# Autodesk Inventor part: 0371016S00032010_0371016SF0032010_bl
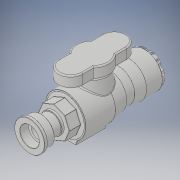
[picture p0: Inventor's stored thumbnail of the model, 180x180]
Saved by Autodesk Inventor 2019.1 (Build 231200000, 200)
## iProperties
Created: 2022-04
Part Number: 0371016S00032010_0371016SF0032010_bl
Material: Generic
Description: PA Ball Valve Series 1 32mm x Free Nut Female 1''
Document SubType Name: Modeling
Designer: Lenora
Density: 1 g/cm^3
Appearance: Default
Author: Lenora
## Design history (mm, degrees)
derived "0371016.ipt"
feature "Solid1::0371016.ipt" dims "ScaleForDerivedMember" = 10
tag "TaggingFeature1"
body "Solid1"
other parameters: "d0" = 192 [user parameter], "d16" = 92.16 [user parameter], "d19" = 1 [user parameter], "d20" = 48 [user parameter], "d22" = 85 deg [user parameter], "d25" = 1 [user parameter], "d34" = 34.56 [user parameter], "d35" = 19.2 [user parameter], "d37" = 0 [user parameter], "d39" = 360 deg [user parameter], "d43" = 33 [user parameter], "d45" = 70 deg [user parameter], "d46" = 70 deg [user parameter], "d48" = 0 [user parameter], "d57" = 2 [user parameter], "d60" = 32 [user parameter], "d63" = 64 [user parameter], "d71" = 9.6 [user parameter], "d72" = 14.4 [user parameter], "d73" = 34.56 [user parameter], "d76" = 64 [user parameter], "d77" = 19.2 [user parameter], "d78" = 51.84 [user parameter], "d79" = 24 [user parameter], "d80" = 100 deg [user parameter], "d81" = 16.32 [user parameter], "d83" = 28.05 [user parameter], "d84" = 14.4 [user parameter], "d85" = 32 [user parameter], "d90" = 0 [user parameter], "d91" = 9.6 [user parameter], "d92" = 45 deg [user parameter], "d93" = 5.12 [user parameter], "d94" = 2.048 [user parameter], "d95" = 2.56 [user parameter], "d96" = 2.56 [user parameter], "d97" = 2.56 [user parameter], "d98" = 2.56 [user parameter], "d111" = 0.5 [user parameter], "d112" = 2 [user parameter], "d114" = 8.96 [user parameter], "d115" = 0 [user parameter], "d117" = 360 deg [user parameter], "d119" = 51.84 [user parameter], "d120" = 57 [user parameter], "d121" = 25 [user parameter], "d122" = 1 [user parameter], "d123" = 89 deg [user parameter], "d124" = 80 deg [user parameter], "d125" = 46 [user parameter], "d127" = 17.6 [user parameter], "d132" = 59.52 [user parameter], "d134" = 0 [user parameter], "d140" = 30.291 [user parameter], "d141" = 21.2037 [user parameter], "d142" = 13.44 [user parameter], "d144" = 43.2 [user parameter], "d145" = 13.44 [user parameter], "d146" = 4.8 [user parameter], "d147" = 33.3201 [user parameter], "d148" = 19.2 [user parameter], "d149" = 38.4 [user parameter], "d150" = 34.56 [user parameter], "d152" = 48 [user parameter], "d153" = 22 [user parameter], "d155" = 0.5 [user parameter], "d" = 25 [user parameter], "DN" = 32 [user parameter], "A1" = 33 [user parameter], "A2" = 64 [user parameter], "H_" = 192 [user parameter], "E_" = 64 [user parameter], "E1" = 57 [user parameter], "B" = 46 [user parameter], "l2" = 22 [user parameter], "G" = 30.291 [user parameter], "E2" = 48 [user parameter]
